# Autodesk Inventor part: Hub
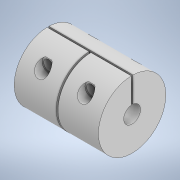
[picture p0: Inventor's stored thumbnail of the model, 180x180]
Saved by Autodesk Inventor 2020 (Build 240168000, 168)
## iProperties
Created: 2023-10
Part Number: Hub
Material: Générique
Document SubType Name: Modeling
Designer: bruno
Density: 1 g/cm^3
Appearance: Par défaut
Author: bruno
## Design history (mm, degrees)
sketch "Esquisse1"
  geometry: C1 r 10 at (0, 0); C2 r 2.5 at (0, 0); 1 further point
  constraints: 2 centre point, 2 coincident
  dimensions: "d0" = 20 diameter of C1; "d1" = 5 diameter of C2
extrude "Extrusion1" new body sketch "Esquisse1" stored distance "d2" = 25; taper "d3" = 0 deg
sketch "Esquisse2"
  geometry: L1 (-15.081, 11.256)-(25.844, 11.256); L2 (25.844, 11.256)-(25.844, 1.363); L3 (25.844, 1.363)-(-15.081, 1.363); L4 (-15.081, 1.363)-(-15.081, 11.256); 1 further point
  constraints: 8 end point, 2 parallel, 1 horizontal, 1 perpendicular
extrude "Extrusion2" cut sketch "Esquisse2" stored distance "d4" = 0.5; taper "d5" = 0 deg
sketch "Esquisse3"
  geometry: L1 (11.282, 0)-(-12.853, 0); L2 (-12.853, 0)-(-12.853, 13.498); L3 (-12.853, 13.498)-(11.282, 13.498); L4 (11.282, 13.498)-(11.282, 0); 1 further point
  constraints: 8 end point, 2 parallel, 1 horizontal, 1 perpendicular
extrude "Extrusion3" cut sketch "Esquisse3" distance "d6" = 0.5; taper "d7" = 0 deg
sketch "Esquisse4"
  geometry: L1 (-12.5, 9.997)-(-12.5, -10) reference; L2 (-12.5, 9.997)-(-0.5, 2.482); L3 (-0.5, 9.997)-(-0.5, -10) reference; L4 (12.5, -10)-(12.5, 9.997) reference; L5 (0, 2.482)-(12.5, 9.997); C1 r 1.5 at (-6.5, 6.239); C2 r 1.5 at (6.25, 6.239); 1 further point
  constraints: 4 end point, 2 centre point, 2 midpoint, 1 point on line
  dimensions: "d8" = 3 diameter of C1; "d9" = 3 diameter of C2
extrude "Extrusion4" cut sketch "Esquisse4" stored distance "d10" = 100; taper "d11" = 0 deg
node "Plan de construction1"
sketch "Esquisse5"
  geometry: C1 r 2 at (-6.25, 6.239); C2 r 2 at (6.5, 6.239); 4 further points
  constraints: 2 centre point, 1 coincident, 1 vertical alignment, 2 other
  dimensions: "d13" = 4 diameter of C1; "d14" = 4 diameter of C2
extrude "Extrusion5" cut sketch "Esquisse5" distance "d15" = 100; taper "d16" = 0 deg
node "Solide1"
other parameters: "d12" = 6.25
